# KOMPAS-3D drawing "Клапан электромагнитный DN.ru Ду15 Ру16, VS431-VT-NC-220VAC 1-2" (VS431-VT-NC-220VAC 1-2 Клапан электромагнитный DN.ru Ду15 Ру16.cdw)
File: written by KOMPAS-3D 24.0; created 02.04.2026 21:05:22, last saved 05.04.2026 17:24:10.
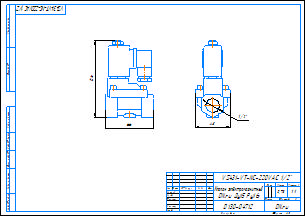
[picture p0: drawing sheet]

Document properties: c3d_UniqueCompID: ef56311e-7521-43dc-8291-0e6108b3d81d; Обозначение: VS400-ET-NC-220VAC 1-2; Наименование: Клапан электромагнитный DN.ru Ду15 Ру16; Автор: artio; Класс точности: c; Знак неуказанной шероховатости: Шероховатость не задана; Рассекать на разрезах: Да; c3d_UniqueCompID: ef56311e-7521-43dc-8291-0e6108b3d81d; Обозначение: VS400-ET-NC-220VAC 3-8; Наименование: Клапан электромагнитный DN.ru Ду10 Ру16; Автор: artio; Класс точности: c; Знак неуказанной шероховатости: Шероховатость не задана; Рассекать на разрезах: Да; Автор: artio; Форматы листов документа: A3; Полное имя файла: VS431-VT-NC-220VAC 1-2 Клапан электромагнитный DN.ru Ду15 Ру16.m3d; Масса: 0.732; Наименование: Клапан электромагнитный DN.ru Ду15 Ру16; Количество листов документа: 1; Примечание: D130-04712

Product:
- Body: Тело 1  | qty 1
    Масса: 1.030062
- Part/product: Клапан электромагнитный DN.ru Ду15 Ру16  | designation VS431-VT-NC-220VAC 1-2
    Масса: 0.732
    Раздел спецификации: Прочие изделия
    Примечание: D130-04712
    additional columns: ef56311e-7521-43dc-8291-0e6108b3d81d; VS400-ET-NC-220VAC 1-2; artio; c; Шероховатость не задана; Да

Views: Вид 1, Спереди, Проекционный вид 2
Referenced files in C:\Users\artio\OneDrive\Рабочий стол\Клапан электромагнитный DN.ru VS4x-xT-NC-x\DN10\: VS400-ET-NC-220VAC 3-8 Клапан электромагнитный DN.ru Ду10 Ру16.m3d, VS400-ET-NC-220VAC 3-8 Клапан электромагнитный DN.ru Ду10 Ру16.cdw
Referenced files in C:\Users\artio\OneDrive\Рабочий стол\Клапан электромагнитный DN.ru\VS431\VS431-VT-NC\VS431-VT-NC-220VAC\Ду15\: VS431-VT-NC-220VAC 1-2 Клапан электромагнитный DN.ru Ду15 Ру16.m3d
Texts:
  VS431-VT-NC-220VAC 1-2
  Линейный размер
  Клапан электромагнитный
  DN.ru Ду15 Ру16
  VS431-VT-NC-220VAC 1/2"
  VS431-VT-NC-220VAC 1/2"-
  Клапан электромагнитный DN.ru Ду15 Ру16
  VS431-VT-NC-220VAC 1-2 Клапан электромагнитный DN.ru Ду15 Ру16
Dimensions and other numbers on the sheet: 0; 3; 2; 4; 48; 1/2"; 66; 106; 1:1; 1; 0,73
